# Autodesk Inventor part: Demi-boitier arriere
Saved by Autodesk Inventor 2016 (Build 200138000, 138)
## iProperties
Created: 2013-08
Part Number: Demi-boitier arriere
Material: Générique
Document SubType Name: Modeling
Designer: hilarion
Density: 1 g/cm^3
Appearance: Par défaut
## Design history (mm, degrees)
node "Demi-boitier arriere1"
node "Demi-boitier arriere"
node "Base1"
